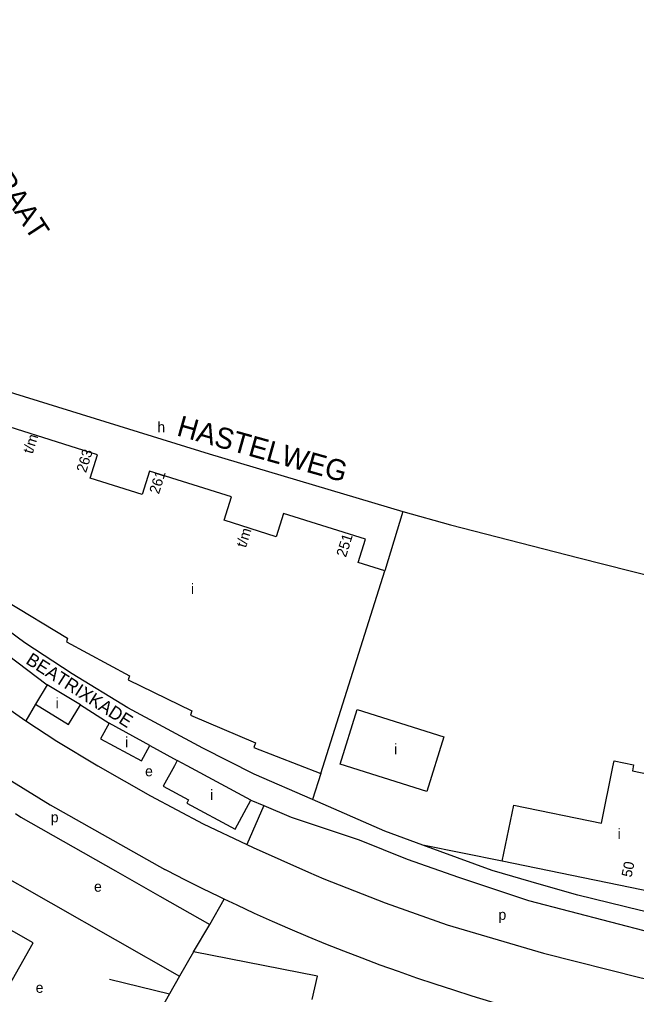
# Model space of a CAD drawing. Extents: x 157699 to 159683, y 381451 to 383293.
# Drawn here: x 158141.2 to 158378.5, y 382912.1 to 383286.9 of the extents above; entities that cross this region are included whole.
import ezdxf

# ---------------------------------------------------------------- set-up
doc = ezdxf.new("R2010")
doc.units = 0
for name, color, linetype in [('BLT_Basislijn', 7, 'Continuous'), ('BLT_Bebouwing', 7, 'Continuous'), ('BLT_Centroide', 7, 'Continuous'), ('BLT_Huisnummer', 7, 'Continuous'), ('BLT_Huisnummer_reeks', 7, 'Continuous'), ('BLT_Straatnaam', 7, 'Continuous'), ('BLT_Straatnaam_hoofdweg', 7, 'Continuous')]:
    doc.layers.add(name, color=color, linetype=linetype)

msp = doc.modelspace()

# ---------------------------------------------------------------- linework, layer by layer
at = {"layer": 'BLT_Basislijn'}
for p, q in [((158288.66, 383097.76), (158281.7, 383074.95)), ((158086.23, 383080.66), (158151.95, 383031.19)), ((158147.37, 383023.66), (158143.64, 383017.24)), ((158164.76, 383023.39), (158175.69, 383016.35)), ((158191.37, 383007.81), (158201.93, 383002.07)), ((158257.13, 382997.05), (158253.94, 382986.99)), ((158230.18, 382986.77), (158235.21, 382984.68)), ((158153.03, 382984.99), (158197.18, 382960.15)), ((158235.21, 382984.68), (158228.69, 382969.7)), ((158326.92, 382963.3), (158296.39, 382969.54)), ((158178.15, 382959.62), (158195.24, 382949.93)), ((158195.24, 382949.93), (158214.49, 382939.03)), ((158214.49, 382939.03), (158219.94, 382948.75)), ((158208.12, 382928.54), (158214.49, 382939.03)), ((158175.88, 382917.97), (158198.98, 382912.38))]:
    msp.add_line(p, q, dxfattribs=at)
for points in [[(158120.96, 383148.8), (158214.2, 383119.98), (158288.66, 383097.76)], [(158288.66, 383097.76), (158306.96, 383092.58), (158356.41, 383079.95)], [(158253.94, 382986.99), (158231.51, 382996.79), (158211.77, 383006.78), (158182.9, 383022.33), (158161.49, 383035.3), (158143.35, 383047.24), (158099.36, 383079.76), (158098.12, 383081.44), (158097.48, 383083.34), (158097.64, 383085.35), (158098.03, 383086.17)], [(158356.41, 383079.95), (158386.16, 383072.35), (158471.46, 383054.68)], [(158075.25, 383067.82), (158088.9, 383056.64), (158119.01, 383034.47), (158143.64, 383017.24)], [(158143.64, 383017.24), (158155.63, 383009.47), (158171.36, 383000), (158191.61, 382988.45), (158211.9, 382977.69), (158228.69, 382969.7)], [(158114.78, 383007.56), (158119.11, 383005.88), (158153.03, 382984.99)], [(158296.39, 382969.54), (158281.8, 382974.89), (158253.94, 382986.99)], [(158235.21, 382984.68), (158245.72, 382980.3), (158271.82, 382971.51), (158290.28, 382964.15), (158310.07, 382957.16), (158337.03, 382948.25), (158384.31, 382935.92), (158498.38, 382911.93), (158639.44, 382881.31), (158654.28, 382876.43), (158670.83, 382865.28)], [(158139.65, 382981.65), (158141.72, 382980.26), (158178.15, 382959.62)], [(158228.69, 382969.7), (158231.07, 382968.56), (158252.34, 382959.15), (158258.33, 382956.61), (158281.83, 382947.29), (158305.67, 382938.88), (158342.79, 382927.93)], [(158342.01, 382954.28), (158323.07, 382959.78), (158296.39, 382969.54)], [(158128.86, 382962.33), (158128.37, 382961.46), (158202.8, 382919.14)], [(158219.94, 382948.75), (158218.17, 382949.6), (158211.46, 382952.87), (158204.79, 382956.22), (158198.16, 382959.64), (158197.18, 382960.15)], [(158419.39, 382935.87), (158380.08, 382944.33), (158355.97, 382950.23), (158342.01, 382954.28)], [(158344.05, 382903.29), (158336.84, 382905.22), (158329.65, 382907.23), (158322.49, 382909.31), (158315.35, 382911.47), (158308.22, 382913.7), (158301.13, 382916.01), (158294.06, 382918.4), (158287.01, 382920.87), (158279.99, 382923.4), (158273, 382926.02), (158266.04, 382928.71), (158259.11, 382931.47), (158252.21, 382934.31), (158245.33, 382937.22), (158238.49, 382940.2), (158231.68, 382943.26), (158224.91, 382946.39), (158219.94, 382948.75)], [(158342.79, 382927.93), (158380.32, 382918.52), (158417.72, 382910.35), (158477.61, 382898.06), (158500, 382893.46)]]:
    msp.add_lwpolyline(points, dxfattribs=at)
at = {"layer": 'BLT_Bebouwing'}
for p, q in [((158151.95, 383031.19), (158147.37, 383023.66)), ((158164.76, 383023.39), (158151.95, 383031.19)), ((158191.37, 383007.81), (158175.69, 383016.35)), ((158231.4, 383007.08), (158257.13, 382997.05)), ((158208.12, 382928.54), (158202.8, 382919.14)), ((158202.8, 382919.14), (158198.98, 382912.38)), ((158198.98, 382912.38), (158190.73, 382897.79))]:
    msp.add_line(p, q, dxfattribs=at)
for points in [[(158281.7, 383074.95), (158271.45, 383078.18), (158274.25, 383087.09), (158242.72, 383097.03), (158239.9, 383088.08), (158219.93, 383094.38), (158222.75, 383103.34), (158191.23, 383113.25), (158188.4, 383104.29), (158168.45, 383110.6), (158171.26, 383119.55), (158121.71, 383135.15), (158118.72, 383125.66), (158123.64, 383124.12)], [(158257.13, 382997.05), (158281.7, 383074.95)], [(158135.98, 383063.43), (158159.73, 383049.09), (158159.29, 383047.71)], [(158159.29, 383047.71), (158183.5, 383034.61), (158183.02, 383033.06)], [(158183.02, 383033.06), (158207.51, 383021.11), (158207.01, 383019.51)], [(158147.37, 383023.66), (158160.13, 383015.83), (158164.76, 383023.39)], [(158175.69, 383016.35), (158172.46, 383010.39), (158188.15, 383001.87), (158191.37, 383007.81)], [(158207.01, 383019.51), (158231.97, 383008.89), (158231.4, 383007.08)], [(158201.93, 383002.07), (158200.81, 383000), (158196.54, 382992.17), (158206.21, 382986.92), (158205.54, 382985.69), (158224.15, 382975.6), (158230.18, 382986.77)], [(158230.18, 382986.77), (158205.76, 383000), (158201.93, 383002.07)], [(158369.45, 382999.63), (158369.92, 383001.9), (158377.43, 383000.36), (158376.97, 382998.11), (158412.27, 382990.82), (158409.3, 382976.31), (158414.6, 382975.23), (158412.42, 382964.59), (158424.69, 382962.1)], [(158331.32, 382984.82), (158365.04, 382977.96), (158369.45, 382999.63)], [(158326.92, 382963.3), (158331.32, 382984.82)], [(158421.02, 382944.05), (158326.92, 382963.3)], [(158119.33, 382923.36), (158136.2, 382913.77), (158146.55, 382931.95), (158123.22, 382945.2), (158122.34, 382943.66)], [(158253.85, 382910.22), (158255.87, 382919.19), (158208.12, 382928.54)]]:
    msp.add_lwpolyline(points, dxfattribs=at)
msp.add_lwpolyline([(158271.11, 383021.66), (158304.49, 383011.1), (158297.87, 382990.18), (158264.51, 383000.68)], close=True, dxfattribs=at)

# ---------------------------------------------------------------- texts
at = {"layer": 'BLT_Centroide'}
for s, p in [('h', (158194.27, 383128.24)), ('i', (158207.2, 383066.09)), ('i', (158155.13, 383022.16)), ('i', (158181.9, 383007.12)), ('i', (158285.3, 383004.47)), ('e', (158189.56, 382995.97)), ('i', (158214.52, 382986.84)), ('p', (158153.28, 382978.27)), ('i', (158371.28, 382971.84)), ('e', (158169.92, 382951.6)), ('p', (158325.46, 382940.78)), ('e', (158147.49, 382912.74))]:
    msp.add_text(s, height=4, dxfattribs=at).set_placement(p)
at = {"layer": 'BLT_Huisnummer'}
msp.add_text('50', height=4, rotation=78.4425, dxfattribs=at).set_placement((158376.62, 382956.92))
at = {"layer": 'BLT_Huisnummer_reeks'}
for s, rotation, p in [('t/m', 72.5665, (158146.26, 383119.68)), ('263', 72.533, (158166.82, 383112.45)), ('261', 72.4677, (158194.85, 383104.21)), ('t/m', 72.5066, (158228.28, 383083.61)), ('251', 72.4913, (158266.77, 383079.93))]:
    msp.add_text(s, height=4, rotation=rotation, dxfattribs=at).set_placement(p)
at = {"layer": 'BLT_Straatnaam'}
msp.add_text('BEATRIXKADE', height=5, rotation=327.4528, dxfattribs=at).set_placement((158143.31, 383039.55))
at = {"layer": 'BLT_Straatnaam_hoofdweg'}
for s, rotation, p in [('ZEELSTERSTRAAT', 303.1944, (158093.09, 383283.13)), ('HASTELWEG', 344.3248, (158201.32, 383127.08))]:
    msp.add_text(s, height=8, rotation=rotation, dxfattribs=at).set_placement(p)

doc.saveas('drawing.dxf')
